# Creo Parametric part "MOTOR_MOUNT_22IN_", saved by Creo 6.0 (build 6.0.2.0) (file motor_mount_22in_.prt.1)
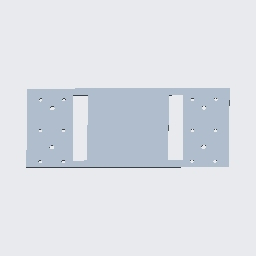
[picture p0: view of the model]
Units: Inch lbm Second (Pro/E Default); INCH, POUND, SECS

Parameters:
  SMT_PART_BEND_ALLOW_FACTOR_TYPE = "Y FACTOR"
  SMT_DFLT_RADIUS_SIDE = "Inside"
  SMT_DFLT_CRNR_REL_TYPE = "V Notch"
  SMT_DFLT_BEND_REL_TYPE = "Rip"
  SMT_DFLT_BEND_REL_DEPTH_TYPE = "Up to Bend"
  SMT_DFLT_EDGE_TREA_TYPE = "Open"
  SMT_DFLT_CRNR_REL_DEPTH_TYPE = "On Origin"
  SMT_DFLT_BEND_REL_LENGTH_TYPE = "Through All"

Other parameters: SMT_THICKNESS, SMT_PART_BEND_ALLOWANCE_FACTOR, SMT_UPDATE_BEND_ALLOW_INFO, SMT_DFLT_BEND_RADIUS, SMT_DFLT_BEND_ANGLE, SMT_DFLT_CRNR_REL_WIDTH, SMT_DFLT_CRNR_REL_DEPTH, SMT_DFLT_BEND_REL_WIDTH, SMT_DFLT_BEND_REL_DEPTH, SMT_DFLT_BEND_REL_ANGLE, SMT_GAP, SMT_DFLT_EDGE_TREA_WIDTH, SMT_DFLT_MITER_CUT_WIDTH, SMT_DFLT_MITER_CUT_OFFSET, SMT_DFLT_BEND_REL_LENGTH, D55

Created from: INLBS_PART_SHEETMETAL.PRT

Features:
  1. datum plane "RIGHT"
  2. datum plane "TOP"
  3. datum plane "FRONT"
  4. coordinate system
  5. sketch "Sketch 1"
  6. fill "Planar 1(First Wall)"
  7. sketch "Sketch 3"
  8. feature "Extrude 2"
  9. sketch "Sketch 2"
  10. feature "Extrude 1"
  11. sketch "Sketch 4"
  12. feature "Extrude 3"

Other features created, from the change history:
  sketch "Sketch 3"
  feature "Extrude 2"
  group "LOCAL_GROUP"
  component interface "Component Interface id 855"

Surfaces: 16 cylinder, 14 plane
